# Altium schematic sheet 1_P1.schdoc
size 307 x 218 mm; Symbol: Drawing-Symbol_A4; Device: Drawing-Symbol_A4; @Project Name: Fubotics_Task; @Page Count: 1; @Update Date: 2026-01-23; @Create Date: 2026-01-23; @Schematic Name: Schematic1; @Page No: 1; @Page Name: P1; Company: EasyEDA.com; Version: V1.0; Page Size: A4; @Create Time: 15:05:50; @Update Time: 20:35:50; Width: 1170; Height: 825; Region Start: 1; X Region Count: 6; Y Region Count: 4; Blade Width: 10; Title Block Position: 3; @Board Name: Board1
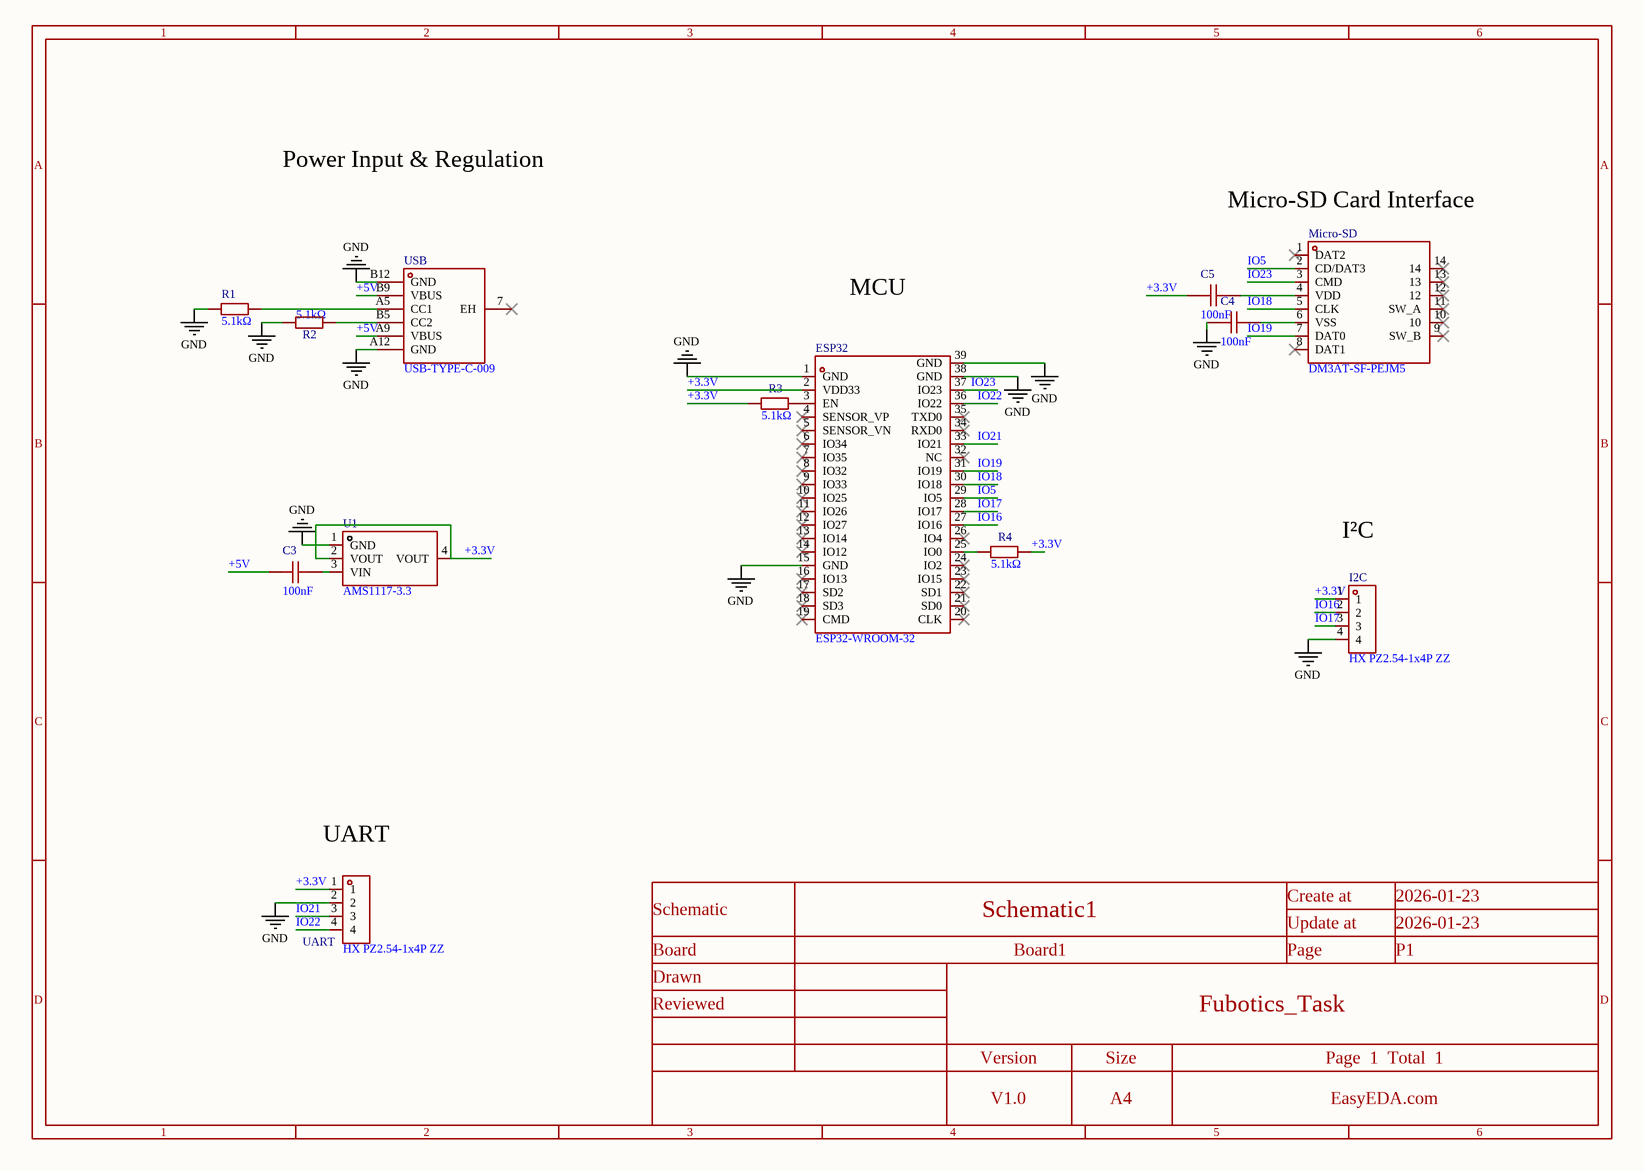
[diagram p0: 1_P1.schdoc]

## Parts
C3  100nF  [C0603]
C4  100nF  [C0603]
C5  100nF  [C0603]
ESP32  ESP32-WROOM-32  [WIFIM-SMD_39P-L25.5-W18.0-P1.27]
I2C  HX PZ2.54-1x4P ZZ  [HDR-TH_4P-P2.54-V-M]
Micro-SD  DM3AT-SF-PEJM5  [SD-SMD_DM3AT-SF-PEJM5]
R1  5.1kΩ  [R0603]
R2  5.1kΩ  [R0603]
R3  5.1kΩ  [R0603]
R4  5.1kΩ  [R0603]
U1  AMS1117-3.3  [SOT-223-3_L6.5-W3.4-P2.30-LS7.0-BR]
UART  HX PZ2.54-1x4P ZZ  [HDR-TH_4P-P2.54-V-M]
USB  USB-TYPE-C-009  [TYPE-C-SMD_TYPE-C-6P]

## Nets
GND: C4.1 ESP32.1(GND) ESP32.15(GND) ESP32.38(GND) ESP32.39(GND) I2C.4 R1.1 R2.1 U1.1(GND) UART.2 USB.A12(GND) USB.B12(GND)
+3.3V: C5.1 ESP32.2(VDD33) I2C.1 R3.1 R4.2 U1.2(VOUT) U1.4(VOUT) UART.1
+5V: C3.1 USB.A9(VBUS) USB.B9(VBUS)
IO5: ESP32.29(IO5) Micro-SD.2(CD/DAT3)
IO16: ESP32.27(IO16) I2C.2
IO17: ESP32.28(IO17) I2C.3
IO18: ESP32.30(IO18) Micro-SD.5(CLK)
IO19: ESP32.31(IO19) Micro-SD.7(DAT0)
IO21: ESP32.33(IO21) UART.3
IO22: ESP32.36(IO22) UART.4
IO23: ESP32.37(IO23) Micro-SD.3(CMD)
NetC3_2: C3.2 U1.3(VIN)
NetC4_2: C4.2 Micro-SD.6(VSS)
NetC5_2: C5.2 Micro-SD.4(VDD)
NetESP32_3: ESP32.3(EN) R3.2
NetESP32_25: ESP32.25(IO0) R4.1
NetR1_2: R1.2 USB.A5(CC1)
NetR2_2: R2.2 USB.B5(CC2)

Not connected (* = marked no-connect by the designer): ESP32 4(SENSOR_VP)* 5(SENSOR_VN)* 6(IO34)* 7(IO35)* 8(IO32)* 9(IO33)* 10(IO25)* 11(IO26)* 12(IO27)* 13(IO14)* 14(IO12)* 16(IO13)* 17(SD2)* 18(SD3)* 19(CMD)* 20(CLK)* 21(SD0)* 22(SD1)* 23(IO15)* 24(IO2)* 26(IO4)* 32(NC)* 34(RXD0)* 35(TXD0)*; Micro-SD 1(DAT2)* 8(DAT1)* 9(SW_B)* 10* 11(SW_A)* 12* 13* 14*; USB 7(EH)*

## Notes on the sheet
- Power Input & Regulation
- (near Micro-SD) Micro-SD Card Interface
- MCU
- I²C
- (near UART) UART

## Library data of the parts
C3-C5 = CC0603KRX7R9BB104: Manufacturer: YAGEO(国巨); Add into BOM: yes; Tolerance: ±10%; Voltage Rating: 50V; Temperature Coefficient: X7R
ESP32 = ESP32-WROOM-32: Symbol: ESP32-WROOM-32_C503587; Add into BOM: yes
I2C UART = HX PZ2.54-1x4P ZZ: Manufacturer: hanxia(韩下); Add into BOM: yes; Pin Structure: 1x4P; Pitch: 2.54mm; Circluar Pins/Square Pins: Pin Header; Current Rating: 3A; Voltage Rating (Max): 1kV
Micro-SD = DM3AT-SF-PEJM5: Manufacturer: HRS(广濑); Add into BOM: yes; Card Connection Mode: Push-Push; Card Type: MicroSD Card (TF Card); Connector Type: Connector and Ejector; Additional Card Detection Pins: No
R1-R4 = 0603WAF5101T5E: Manufacturer: UNI-ROYAL(厚声); Add into BOM: yes; Tolerance: ±1%; Power(Watts): 100mW; Voltage-Supply(Max): 75V; Temperature Coefficient: ±100ppm/℃
U1 = AMS1117-3.3_C6186: Manufacturer: AMS; Add into BOM: yes; Output Type: Fixed; Voltage - Supply: 16V; Output Voltage: 3.3V; Output Current: 1A; Power Supply Rejection Ratio (PSRR): 72dB@(120Hz); Voltage Dropout: 1.1V@(800mA); standby current: 5mA; Noise: 0.003%Vout; Output Configuration: Positive; Number of Outputs: 1
USB = USB-TYPE-C-009: Manufacturer: DEALON(德艺隆); Add into BOM: yes; Connector Type: Type-C; Gender: Female; Number of Contacts: 6P; Number of Ports: 1; Current Rating-Power: 5A; Voltage Rating: 5V; Connect-Disconnect Life: 10,000 cycles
